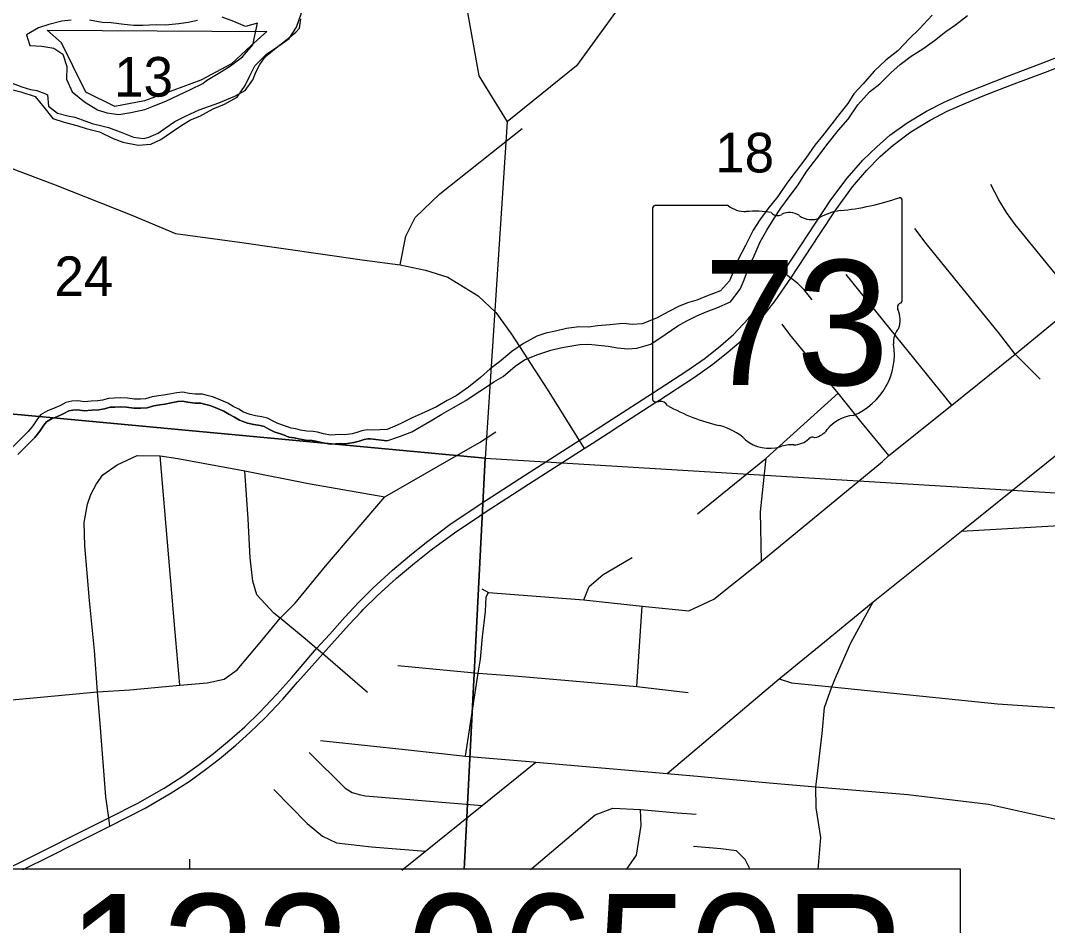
# Model space of a CAD drawing. Extents: x 0 to 34, y 0 to 22.
# Drawn here: x 7.278 to 8.362, y 18.183 to 19.138 of the extents above; entities that cross this region are included whole.
import ezdxf

# ---------------------------------------------------------------- set-up
doc = ezdxf.new("R2010")
doc.units = 0
for name, color, linetype in [('GM_X_City_Street', 7, 'Continuous'), ('GM_X_Corporation', 7, 'Continuous'), ('GM_X_Major_River', 7, 'Continuous'), ('GM_X_Minor_River', 7, 'Continuous'), ('GM_X_Section_Text', 7, 'Continuous'), ('GM_X_State_Location', 7, 'Continuous'), ('GM_X_State_Route', 7, 'Continuous'), ('GM_X_State_Shield', 7, 'Continuous'), ('SH_Text', 7, 'Continuous')]:
    doc.layers.add(name, color=color, linetype=linetype)

msp = doc.modelspace()

# ---------------------------------------------------------------- linework, layer by layer
at = {"layer": 'GM_X_City_Street'}
for p, q in [((8.2608, 18.7319), (8.1494, 18.8696)), ((8.1944, 18.6785), (8.183, 18.6923)), ((8.2709, 18.5986), (8.3877, 18.6055)), ((7.9282, 18.4348), (7.934, 18.5197)), ((7.4565, 18.2415), (7.4565, 18.2527))]:
    msp.add_line(p, q, dxfattribs=at)
for points in [[(7.9604, 18.3429), (8.0785, 18.443), (8.1263, 18.4819), (8.1779, 18.5241), (8.2709, 18.5986), (8.3967, 18.6996), (8.5001, 18.7867), (8.6479, 18.9068), (8.7952, 19.025), (8.88, 19.0943)], [(7.9831, 18.5148), (8.0096, 18.527), (8.0601, 18.5672), (8.1876, 18.6723), (8.1944, 18.6785), (8.2608, 18.7319), (8.3278, 18.7857), (8.3946, 18.8403), (8.4606, 18.8937), (8.4843, 18.9125), (8.5075, 18.931), (8.526, 18.9454), (8.5589, 18.9711), (8.5934, 19.0006), (8.6038, 19.0083), (8.6182, 19.0203), (8.6383, 19.0363), (8.6474, 19.0438), (8.6507, 19.0475), (8.654, 19.0528)], [(7.6785, 18.8798), (7.6846, 18.91), (7.6942, 18.9298), (7.7205, 18.9547), (7.8072, 19.0237)], [(7.1744, 18.9974), (7.2247, 18.9906), (7.2376, 18.9889), (7.2669, 18.9824), (7.3145, 18.9643), (7.3951, 18.9322), (7.4412, 18.9129), (7.509, 18.9037), (7.6408, 18.8847), (7.6785, 18.8798), (7.7053, 18.8743), (7.7287, 18.8668), (7.7608, 18.8473), (7.7795, 18.8294), (7.7959, 18.8068), (7.8336, 18.7488), (7.8673, 18.6946), (7.8728, 18.686)], [(8.3946, 18.8403), (8.3276, 18.9225), (8.3187, 18.9352), (8.3103, 18.9485), (8.302, 18.9648)], [(8.3541, 18.7591), (8.3278, 18.7857), (8.31, 18.8084), (8.2594, 18.8707), (8.2336, 18.9024), (8.2219, 18.9181)], [(8.1133, 18.8428), (8.1048, 18.8535), (8.0982, 18.86), (8.091, 18.8659), (8.0829, 18.8723)], [(8.183, 18.6923), (8.1648, 18.7144), (8.1407, 18.7443), (8.1202, 18.7694), (8.09, 18.8065), (8.0817, 18.8173)], [(7.9922, 18.6171), (8.0648, 18.6759), (8.1407, 18.7443)], [(7.1651, 18.4119), (7.1839, 18.4133), (7.2197, 18.416), (7.3591, 18.4293), (7.393, 18.4314), (7.4458, 18.4361), (7.4749, 18.4387), (7.4927, 18.4426), (7.5065, 18.4525), (7.5324, 18.4835), (7.552, 18.5069), (7.5675, 18.5228), (7.5998, 18.5617), (7.6623, 18.6351), (7.7187, 18.6673), (7.7624, 18.6924), (7.7796, 18.7036)], [(7.3719, 18.2874), (7.3709, 18.2961), (7.3679, 18.3183), (7.3619, 18.3959), (7.3591, 18.4293), (7.3557, 18.4727), (7.3507, 18.5255), (7.3457, 18.5832), (7.3449, 18.6079), (7.3484, 18.6273), (7.3521, 18.6373), (7.358, 18.6488), (7.3647, 18.6583), (7.3797, 18.6689), (7.4008, 18.6787), (7.4252, 18.6783), (7.4437, 18.6753), (7.5144, 18.6624), (7.5818, 18.6491), (7.6623, 18.6351)], [(7.4458, 18.4361), (7.4405, 18.4961), (7.4252, 18.6783)], [(8.0601, 18.5672), (8.0587, 18.6193), (8.0648, 18.6759)], [(7.6439, 18.4285), (7.5969, 18.4693), (7.5903, 18.4748), (7.576, 18.4869), (7.552, 18.5069), (7.5453, 18.5122), (7.5271, 18.5316), (7.523, 18.546), (7.5203, 18.5706), (7.5179, 18.6119), (7.5144, 18.6624)], [(7.8725, 18.5262), (7.878, 18.5405), (7.8929, 18.5529), (7.9233, 18.5709)], [(7.7648, 18.5377), (7.7716, 18.534), (7.8725, 18.5262), (7.934, 18.5197), (7.9831, 18.5148)], [(7.7475, 18.3614), (7.761, 18.4489), (7.7632, 18.4636), (7.7653, 18.4871), (7.7687, 18.514), (7.7693, 18.5296), (7.7716, 18.534)], [(8.1187, 18.3401), (8.1238, 18.3852), (8.1263, 18.4125), (8.1341, 18.4343), (8.139, 18.4465), (8.1542, 18.481), (8.1779, 18.5241)], [(7.676, 18.4571), (7.761, 18.4489), (7.799, 18.4461), (7.8605, 18.4407), (7.9282, 18.4348), (7.9824, 18.4283)], [(8.0785, 18.443), (8.0916, 18.4385), (8.1341, 18.4343), (8.3091, 18.4164), (8.4148, 18.4093), (8.463, 18.4055), (8.467, 18.4057)], [(7.5944, 18.3779), (7.6439, 18.3725), (7.6838, 18.3682), (7.7475, 18.3614), (7.8193, 18.3552), (7.8216, 18.355), (7.8546, 18.3522), (7.9604, 18.3429), (7.9962, 18.3397), (8.0146, 18.3381), (8.0724, 18.3329), (8.1174, 18.3288), (8.2145, 18.3208), (8.2997, 18.3107), (8.3851, 18.2916), (8.3945, 18.2887), (8.4179, 18.2828), (8.4549, 18.2717), (8.5013, 18.2607), (8.559, 18.2414), (8.5677, 18.2397)], [(7.5826, 18.3652), (7.6206, 18.3275), (7.6278, 18.3228), (7.6354, 18.3207), (7.642, 18.3195), (7.7649, 18.3092)], [(7.6804, 18.2409), (7.7053, 18.261), (7.7649, 18.3092), (7.8216, 18.355)], [(8.1196, 18.2415), (8.1227, 18.2753), (8.1178, 18.3068), (8.1174, 18.3288), (8.1187, 18.3401)], [(7.5451, 18.326), (7.5804, 18.2903), (7.5965, 18.2768), (7.6112, 18.2699), (7.6484, 18.2655), (7.7053, 18.261)], [(7.8162, 18.2415), (7.8176, 18.2425), (7.8842, 18.2993), (7.9029, 18.3062), (7.9323, 18.3049), (7.971, 18.3016), (7.991, 18.3002)], [(7.9175, 18.2415), (7.9279, 18.2569), (7.933, 18.2882), (7.9323, 18.3049)], [(8.0474, 18.2415), (8.0472, 18.2431), (8.0426, 18.2523), (8.0336, 18.2614), (8.017, 18.2635), (7.9883, 18.266)]]:
    msp.add_lwpolyline(points, dxfattribs=at)
at = {"layer": 'GM_X_Corporation'}
for points in [[(7.6771, 19.5524), (7.7616, 19.0792), (7.7916, 19.0309), (7.7682, 18.6757), (6.7468, 18.7711)], [(8.0039, 19.2819), (7.8648, 19.09), (7.7916, 19.0309), (7.7682, 18.6757), (8.8396, 18.6106)], [(7.2672, 19.0724), (7.2793, 19.0676), (7.2883, 19.0651), (7.2951, 19.0638), (7.3034, 19.0606), (7.3064, 19.0594), (7.3072, 19.0473), (7.3106, 19.0449), (7.3169, 19.0399), (7.3278, 19.037), (7.335, 19.0357), (7.3429, 19.0329), (7.3534, 19.0292), (7.3636, 19.0267), (7.3708, 19.0247), (7.3828, 19.0203), (7.3971, 19.0147), (7.4076, 19.0133), (7.4133, 19.0147), (7.4229, 19.0187), (7.4306, 19.0242), (7.4406, 19.0312), (7.4525, 19.0373), (7.4662, 19.0435), (7.4872, 19.051), (7.504, 19.0578), (7.5148, 19.064), (7.523, 19.0752), (7.5266, 19.0839), (7.5305, 19.0913), (7.5364, 19.0999), (7.551, 19.1117), (7.5607, 19.1191), (7.5684, 19.1254), (7.5723, 19.1298), (7.5736, 19.1397)], [(7.7361, 18.0529), (7.7161, 17.6636), (6.6697, 17.7728), (6.7468, 18.7711), (7.7682, 18.6757), (7.7459, 18.2415)], [(7.7459, 18.2415), (7.7682, 18.6757), (8.8396, 18.6106), (8.7511, 17.5795), (7.7161, 17.6636), (7.7361, 18.0529)]]:
    msp.add_lwpolyline(points, dxfattribs=at)
msp.add_lwpolyline([(7.5377, 19.126), (7.5209, 19.111), (7.5003, 19.0921), (7.468, 19.0748), (7.4396, 19.0643), (7.4085, 19.0531), (7.3773, 19.047), (7.3467, 19.062), (7.3328, 19.0899), (7.3211, 19.1143), (7.3059, 19.1276)], close=True, dxfattribs=at)
at = {"layer": 'GM_X_Major_River'}
for points in [[(7.2623, 19.0662), (7.2781, 19.0625), (7.2932, 19.0577), (7.3024, 19.0464), (7.3117, 19.0345), (7.3237, 19.0304), (7.3373, 19.0271), (7.3471, 19.0239), (7.3611, 19.0202), (7.3754, 19.0131), (7.3859, 19.0095), (7.4021, 19.0061), (7.4154, 19.0074), (7.4258, 19.0121), (7.4373, 19.0199), (7.4469, 19.0265), (7.4573, 19.0328), (7.4669, 19.0368), (7.481, 19.0445), (7.4929, 19.0496), (7.5063, 19.0569), (7.5149, 19.0693), (7.5197, 19.0794), (7.5252, 19.09), (7.5376, 19.1027), (7.5514, 19.1119), (7.5614, 19.1189), (7.5689, 19.1309), (7.5745, 19.146)], [(7.3312, 19.1383), (7.3214, 19.1369), (7.3076, 19.1334), (7.2966, 19.1302), (7.2839, 19.1228), (7.2875, 19.1114), (7.3003, 19.1107), (7.3128, 19.1086), (7.3225, 19.1023), (7.3265, 19.0893), (7.3262, 19.076), (7.3324, 19.0626), (7.3454, 19.0521), (7.3589, 19.0434), (7.3687, 19.0402), (7.3816, 19.0384), (7.3941, 19.0405), (7.409, 19.044), (7.4197, 19.0479), (7.4312, 19.0527), (7.4446, 19.0589), (7.4572, 19.0651), (7.4702, 19.0713)], [(7.4644, 19.1379), (7.4548, 19.1355), (7.4449, 19.1341), (7.4309, 19.1329), (7.421, 19.1331), (7.407, 19.1326), (7.3975, 19.1324), (7.3873, 19.1337), (7.3733, 19.1352), (7.3638, 19.1357), (7.3506, 19.1383)], [(7.4702, 19.0713), (7.4741, 19.0743), (7.4898, 19.0838), (7.4994, 19.0901), (7.5121, 19.0994), (7.523, 19.1121), (7.528, 19.1348)], [(7.528, 19.1348), (7.5151, 19.1316), (7.503, 19.1368), (7.4906, 19.1412)]]:
    msp.add_lwpolyline(points, dxfattribs=at)
at = {"layer": 'GM_X_Minor_River'}
for points in [[(7.6646, 18.694), (7.6787, 18.699), (7.6909, 18.7037), (7.7102, 18.7147), (7.7225, 18.7224), (7.7348, 18.7294), (7.7478, 18.7367), (7.7575, 18.7434), (7.7675, 18.7496), (7.7775, 18.7562), (7.7871, 18.7621), (7.7999, 18.7729), (7.8099, 18.7795), (7.8229, 18.7849), (7.8374, 18.7899), (7.8477, 18.7924), (7.8576, 18.7941), (7.8683, 18.7957), (7.8778, 18.7963), (7.8876, 18.795), (7.8982, 18.794), (7.908, 18.7923), (7.919, 18.7913), (7.9285, 18.7919), (7.943, 18.7961), (7.9584, 18.8064), (7.9715, 18.8156), (7.9811, 18.8208), (7.9915, 18.8259), (8.0015, 18.8302), (8.0126, 18.8345), (8.0271, 18.8407), (8.0373, 18.8542), (8.0417, 18.8639), (8.0461, 18.8764), (8.0521, 18.8895), (8.0585, 18.9042), (8.0656, 18.9166), (8.0735, 18.9294), (8.0805, 18.9398), (8.0891, 18.9518), (8.0981, 18.9634), (8.1079, 18.9788), (8.1185, 18.9926), (8.1302, 19.0083), (8.1411, 19.0221), (8.1513, 19.0337), (8.1615, 19.0487), (8.1739, 19.0625), (8.1847, 19.071), (8.1964, 19.0825), (8.2064, 19.0914), (8.218, 19.1003), (8.2303, 19.108), (8.2426, 19.1165), (8.2546, 19.1261), (8.2646, 19.1331), (8.2774, 19.1431)], [(8.2402, 19.1435), (8.2262, 19.1286), (8.2161, 19.1189), (8.2037, 19.1059), (8.1913, 19.0959), (8.1789, 19.0844), (8.1673, 19.071), (8.1575, 19.0605), (8.1509, 19.05), (8.1427, 19.0396), (8.1317, 19.0257), (8.1243, 19.016), (8.1161, 19.0063), (8.1067, 18.9925), (8.0966, 18.979), (8.0868, 18.9659), (8.077, 18.9521), (8.0665, 18.939), (8.0582, 18.9274), (8.0512, 18.9165), (8.0432, 18.9004), (8.0357, 18.8861), (8.0317, 18.8763), (8.0261, 18.8631), (8.0167, 18.8523), (8.0018, 18.8469), (7.9915, 18.8426), (7.9819, 18.8397), (7.9724, 18.8358), (7.962, 18.8307), (7.949, 18.8237), (7.934, 18.8176), (7.9238, 18.817), (7.9135, 18.818), (7.8998, 18.8164), (7.8869, 18.8155), (7.8774, 18.8142), (7.8672, 18.8144), (7.8542, 18.8127), (7.8424, 18.8099), (7.8321, 18.8079), (7.8226, 18.8047), (7.8087, 18.797), (7.7964, 18.7885), (7.7833, 18.7774), (7.7736, 18.77), (7.7632, 18.7611), (7.7508, 18.7507), (7.7377, 18.7415), (7.7281, 18.7367), (7.7169, 18.7301), (7.7008, 18.7225), (7.6913, 18.7185), (7.6786, 18.7119), (7.6648, 18.7061)], [(7.6648, 18.7061), (7.6493, 18.7054), (7.6436, 18.7058), (7.638, 18.7047), (7.6327, 18.7028), (7.6277, 18.7016), (7.6202, 18.7005), (7.6153, 18.7009), (7.61, 18.7005), (7.605, 18.7001), (7.5975, 18.7016), (7.5914, 18.7032), (7.5865, 18.7039), (7.58, 18.7043), (7.5732, 18.7054), (7.5683, 18.7066), (7.5633, 18.7073), (7.5584, 18.7092), (7.5493, 18.7123), (7.5444, 18.7149), (7.5383, 18.718), (7.5326, 18.7195), (7.5258, 18.7206), (7.5201, 18.7218), (7.5133, 18.7244), (7.5083, 18.7275), (7.5023, 18.7305), (7.4966, 18.7339), (7.4916, 18.7358), (7.4867, 18.7381), (7.4803, 18.7404), (7.4746, 18.7419), (7.4697, 18.7434), (7.4624, 18.7434), (7.4556, 18.7441), (7.4492, 18.7453), (7.4427, 18.7449), (7.4351, 18.7434), (7.4287, 18.7423), (7.4234, 18.7415), (7.4166, 18.7404), (7.4097, 18.7385), (7.4044, 18.7381), (7.398, 18.7381), (7.3908, 18.7392), (7.3832, 18.7396), (7.3767, 18.7392), (7.3707, 18.7388), (7.3642, 18.7369), (7.3593, 18.7362), (7.3525, 18.7358), (7.3453, 18.7354), (7.3384, 18.7362), (7.332, 18.7358), (7.3255, 18.7347), (7.3191, 18.7312), (7.3126, 18.7282), (7.3062, 18.7259), (7.299, 18.7214), (7.2948, 18.7164), (7.2906, 18.71), (7.2857, 18.7039), (7.2679, 18.6861)], [(7.275, 18.6798), (7.2928, 18.6976), (7.2983, 18.7044), (7.3024, 18.7108), (7.3053, 18.7142), (7.3104, 18.7174), (7.3162, 18.7194), (7.3233, 18.7228), (7.3287, 18.7256), (7.3331, 18.7264), (7.3382, 18.7267), (7.345, 18.7259), (7.353, 18.7263), (7.3603, 18.7268), (7.3663, 18.7277), (7.3723, 18.7295), (7.3773, 18.7298), (7.3832, 18.7301), (7.3898, 18.7298), (7.3972, 18.7286), (7.4048, 18.7286), (7.4114, 18.7291), (7.4186, 18.7311), (7.4248, 18.7321), (7.4302, 18.7329), (7.4369, 18.7341), (7.4439, 18.7355), (7.4486, 18.7358), (7.4543, 18.7348), (7.4619, 18.7339), (7.4682, 18.7339), (7.472, 18.7328), (7.4775, 18.7313), (7.4831, 18.7293), (7.488, 18.7271), (7.4924, 18.7254), (7.4977, 18.7222), (7.5037, 18.7192), (7.509, 18.7159), (7.5174, 18.7126), (7.5241, 18.7113), (7.5306, 18.7102), (7.5349, 18.7091), (7.54, 18.7065), (7.5455, 18.7036), (7.5552, 18.7003), (7.5609, 18.6981), (7.5665, 18.6973), (7.5713, 18.6962), (7.579, 18.6949), (7.5855, 18.6945), (7.5895, 18.6939), (7.5954, 18.6924), (7.6045, 18.6906), (7.6107, 18.6911), (7.6152, 18.6914), (7.6205, 18.691), (7.6295, 18.6923), (7.6353, 18.6937), (7.6405, 18.6955), (7.6443, 18.6963), (7.6472, 18.6961), (7.6646, 18.694)], [(7.6646, 18.694), (7.6472, 18.6961), (7.6443, 18.6963), (7.6405, 18.6955), (7.6353, 18.6937), (7.6295, 18.6923), (7.6205, 18.691), (7.6152, 18.6914), (7.6107, 18.6911), (7.6045, 18.6906), (7.5954, 18.6924), (7.5895, 18.6939), (7.5855, 18.6945), (7.579, 18.6949), (7.5713, 18.6962), (7.5665, 18.6973), (7.5609, 18.6981), (7.5552, 18.7003), (7.5455, 18.7036), (7.54, 18.7065), (7.5349, 18.7091), (7.5306, 18.7102), (7.5241, 18.7113), (7.5174, 18.7126), (7.509, 18.7159), (7.5037, 18.7192), (7.4977, 18.7222), (7.4924, 18.7254), (7.488, 18.7271), (7.4831, 18.7293), (7.4775, 18.7313), (7.472, 18.7328), (7.4682, 18.7339), (7.4619, 18.7339), (7.4543, 18.7348), (7.4486, 18.7358), (7.4439, 18.7355), (7.4369, 18.7341), (7.4302, 18.7329), (7.4248, 18.7321), (7.4186, 18.7311), (7.4114, 18.7291), (7.4048, 18.7286), (7.3972, 18.7286), (7.3898, 18.7298), (7.3832, 18.7301), (7.3773, 18.7298), (7.3723, 18.7295), (7.3663, 18.7277), (7.3603, 18.7268), (7.353, 18.7263), (7.345, 18.7259), (7.3382, 18.7267), (7.3331, 18.7264), (7.3287, 18.7256), (7.3233, 18.7228), (7.3162, 18.7194), (7.3104, 18.7174), (7.3053, 18.7142), (7.3024, 18.7108), (7.2983, 18.7044), (7.2928, 18.6976), (7.275, 18.6798)]]:
    msp.add_lwpolyline(points, dxfattribs=at)
at = {"layer": 'GM_X_State_Route'}
msp.add_line((7.8812, 18.6914), (7.8979, 18.7022), dxfattribs=at)
for points in [[(7.2619, 18.2415), (7.2804, 18.2508), (7.3072, 18.2641), (7.3343, 18.2778), (7.3709, 18.2961), (7.4017, 18.3117), (7.4293, 18.3275), (7.449, 18.3402), (7.4665, 18.3525), (7.4814, 18.3639), (7.4985, 18.3781), (7.5144, 18.3922), (7.5305, 18.4077), (7.5484, 18.4267), (7.564, 18.4444), (7.5903, 18.4748), (7.6042, 18.4902), (7.6201, 18.5079), (7.6348, 18.5239), (7.6497, 18.5385), (7.6703, 18.5576), (7.6882, 18.5728), (7.7063, 18.5873), (7.7311, 18.6057), (7.7629, 18.6273), (7.8109, 18.6582), (7.8673, 18.6946), (7.9022, 18.717), (7.9449, 18.7444), (7.9811, 18.7679), (8.0004, 18.7813), (8.0166, 18.7943), (8.0304, 18.8062), (8.046, 18.8227), (8.0563, 18.8351), (8.0664, 18.8484), (8.0829, 18.8723), (8.0939, 18.889), (8.1161, 18.9229), (8.1331, 18.9485), (8.1504, 18.9715), (8.1668, 18.9904), (8.1815, 19.0045), (8.1953, 19.0166), (8.2138, 19.0299), (8.2341, 19.0422), (8.2529, 19.0517), (8.2734, 19.0606), (8.2923, 19.0682), (8.3189, 19.0786), (8.3542, 19.0921), (8.3904, 19.106)], [(7.9475, 18.7341), (7.9516, 18.7368), (7.9892, 18.7612), (8.0085, 18.7749), (8.0247, 18.7879), (8.0385, 18.7998), (8.054, 18.8163), (8.0643, 18.8287), (8.0744, 18.842), (8.091, 18.8659), (8.1213, 18.9119), (8.1385, 18.938), (8.156, 18.9621), (8.171, 18.9798), (8.1852, 18.9941), (8.1989, 19.0063), (8.2175, 19.0201), (8.2378, 19.0324), (8.256, 19.0419), (8.2762, 19.051), (8.294, 19.0581), (8.3239, 19.0697), (8.3596, 19.0833), (8.3956, 19.0972)], [(7.8979, 18.7022), (7.9104, 18.7102), (7.9475, 18.7341)], [(7.8138, 18.6483), (7.8728, 18.686), (7.8812, 18.6914)], [(7.6372, 18.5137), (7.6393, 18.5159), (7.6542, 18.5304), (7.6747, 18.5492), (7.6936, 18.5649), (7.7111, 18.5789), (7.7359, 18.597), (7.7625, 18.615), (7.7683, 18.6189), (7.8138, 18.6483)], [(7.5768, 18.4467), (7.5969, 18.4693), (7.6245, 18.5001), (7.6372, 18.5137)], [(7.28, 18.2415), (7.2813, 18.2421), (7.3082, 18.2554), (7.3353, 18.2691), (7.3719, 18.2874), (7.4092, 18.3063), (7.4358, 18.3219), (7.4556, 18.3346), (7.473, 18.347), (7.4879, 18.3584), (7.5049, 18.373), (7.5198, 18.3861), (7.536, 18.4018), (7.5545, 18.4213), (7.5702, 18.4392), (7.5768, 18.4467)]]:
    msp.add_lwpolyline(points, dxfattribs=at)
at = {"layer": 'GM_X_State_Shield'}
for p, q in [((7.9449, 18.939), (7.9449, 18.7389)), ((8.0247, 18.9424), (7.9475, 18.9424)), ((8.2085, 18.8427), (8.2085, 18.9474)), ((8.2085, 18.8427), (8.2085, 18.8427))]:
    msp.add_line(p, q, dxfattribs=at)
for centre, radius, start, end in [((8.1146, 19.2152), 0.2796, 275.8445, 288.9065), ((8.2056, 18.9478), 0.00294, 351.8621, 97.738), ((7.9479, 18.9394), 0.00305, 98.1301, 188.1301), ((8.0431, 18.9656), 0.0296, 231.6195, 271.1119), ((8.0529, 18.8301), 0.1064, 80.4867, 94.9883), ((8.077, 18.9404), 0.00855, 219.7921, 297.1024), ((8.0896, 18.9173), 0.0178, 54.4667, 119.1411), ((8.1125, 18.949), 0.0214, 233.8562, 294.8282), ((8.1503, 18.8813), 0.0563, 97.3462, 120.7689), ((8.2054, 18.8423), 0.00314, 289.6038, 7.7341), ((8.2079, 18.835), 0.00454, 107.944, 210.337), ((8.179, 18.8218), 0.0273, 340.033, 23.6496), ((8.219, 18.7989), 0.0198, 136.8065, 186.9296), ((8.1303, 18.7856), 0.0699, 292.3089, 8.9858), ((7.9479, 18.7384), 0.00308, 171.9584, 258.3066), ((7.9484, 18.7589), 0.0235, 267.339, 280.6039), ((7.9532, 18.7273), 0.00848, 29.7484, 93.2717), ((8.0603, 18.9071), 0.2019, 240.4129, 257.1985), ((8.0001, 18.6489), 0.0632, 47.1842, 75.836), ((8.1598, 18.6827), 0.0383, 94.4031, 142.5768), ((8.1112, 18.7195), 0.0226, 282.8732, 323.2771), ((8.0684, 18.7263), 0.0401, 230.7004, 286.2918), ((8.0915, 18.6571), 0.0329, 85.6951, 111.2099), ((8.0945, 18.7113), 0.0214, 268.777, 315.5493), ((8.1138, 18.6919), 0.00601, 65.7517, 132.6484)]:
    msp.add_arc(centre, radius, start, end, dxfattribs=at)
at = {"layer": 'SH_Text'}
msp.add_lwpolyline([(8.27, 18.2419), (6.8929, 18.2419), (6.8929, 18.0533), (8.27, 18.0533)], close=True, dxfattribs=at)

# ---------------------------------------------------------------- texts
at = {"layer": 'GM_X_Section_Text'}
for s, p in [('13', (7.3765, 19.0574)), ('18', (8.011, 18.9774)), ('24', (7.3135, 18.8469))]:
    msp.add_text(s, height=0.04186, rotation=0, dxfattribs=at).set_placement(p)
at = {"layer": 'GM_X_State_Location'}
for s in ['s', 'r']:
    msp.add_text(s, height=0.000189, dxfattribs=at).set_placement((8.0737, 18.8256))
msp.add_text('73', height=0.000189, rotation=0, dxfattribs=at).set_placement((8.026, 18.8118))
at = {"layer": 'GM_X_State_Shield'}
msp.add_text('73', height=0.13184, dxfattribs=at).set_placement((7.9985, 18.753))
at = {"layer": 'SH_Text'}
msp.add_text('BUT-122-0650R', height=0.133892, dxfattribs=at).set_placement((6.909, 18.0817))

doc.saveas('drawing.dxf')
